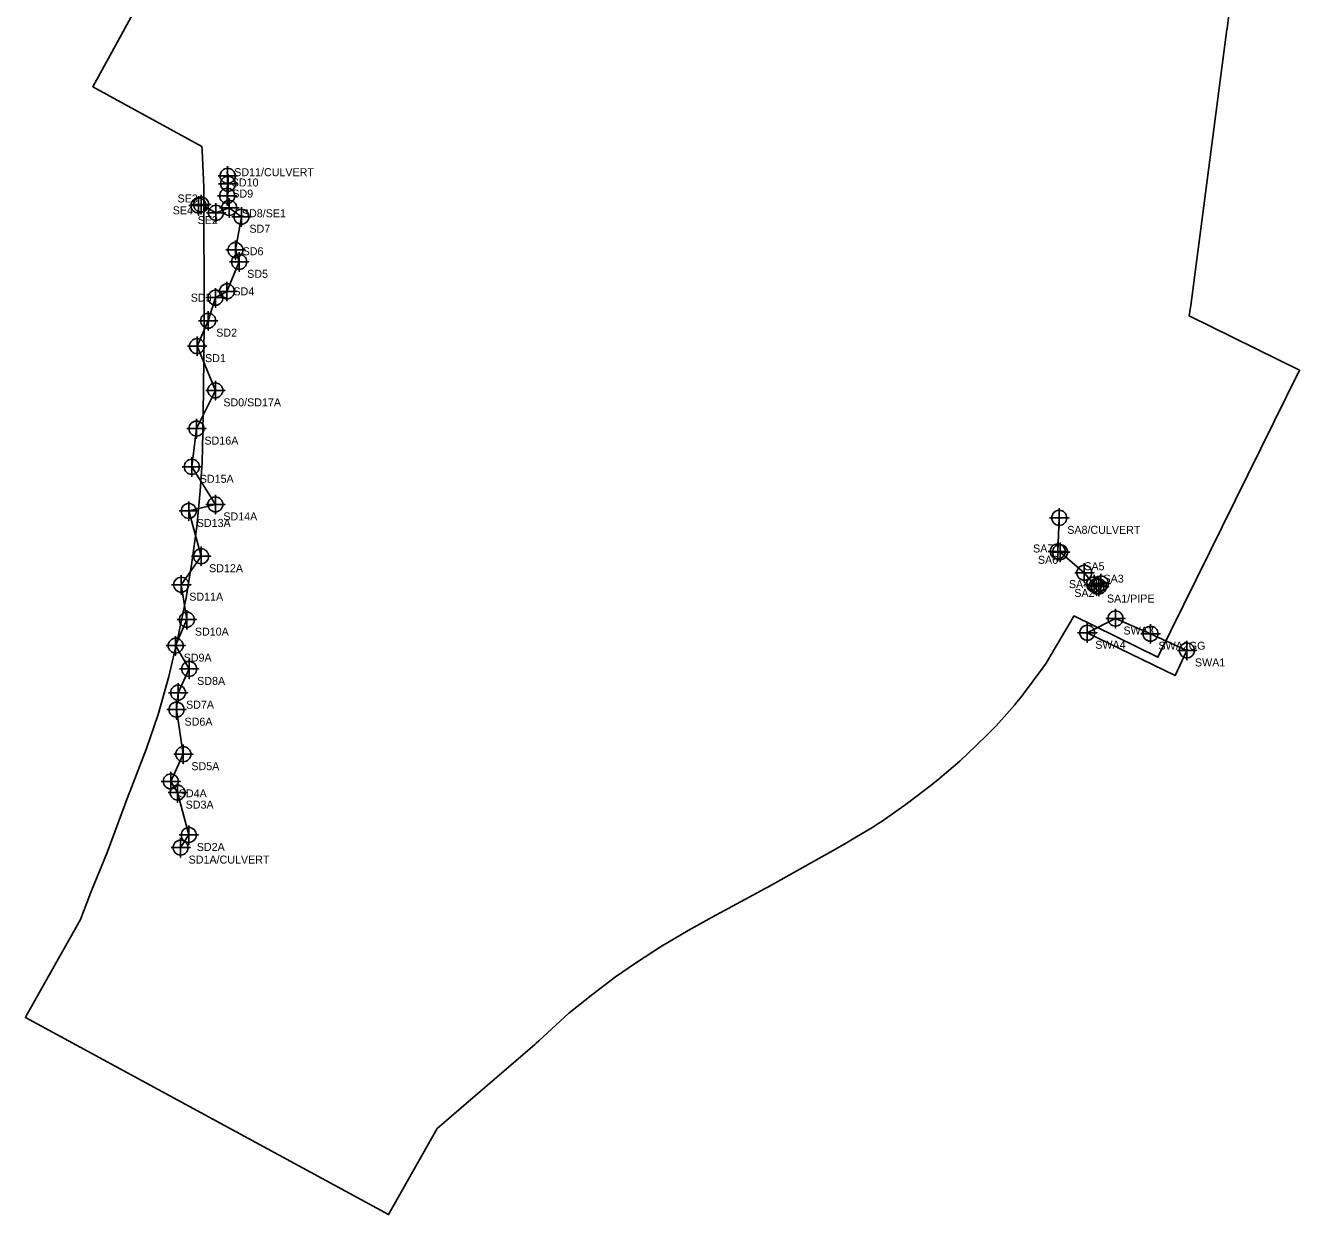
# Model space of a CAD drawing. Extents: x 2074690 to 2076562, y 742141 to 745115.
# Drawn here: x 2074690 to 2076283, y 742141 to 743628 of the extents above; entities that cross this region are included whole.
import ezdxf

# ---------------------------------------------------------------- set-up
doc = ezdxf.new("R2010")
doc.units = 0
for name, color, linetype in [('Default', 7, 'Continuous'), ('Exist Hydro Jurisdictional Stream or Body of Water Mitigable', 7, 'Continuous'), ('Exist Hydro Jurisdictional Stream or Body of Water Mitigable Cogo Comment', 7, 'Continuous'), ('Exist Hydro Jurisdictional Stream or Body of Water Mitigable Cogo Point CELL', 7, 'Continuous'), ('Exist Hydro Jurisdictional Stream or Body of Water NonMitigable', 7, 'Continuous'), ('Exist Hydro Jurisdictional Stream or Body of Water NonMitigable Cogo Comment', 7, 'Continuous'), ('Exist Hydro Jurisdictional Stream or Body of Water NonMitigable Cogo Point CELL', 7, 'Continuous')]:
    doc.layers.add(name, color=color, linetype=linetype)

msp = doc.modelspace()

# ---------------------------------------------------------------- linework, layer by layer
at = {"layer": 'Default'}
msp.add_lwpolyline([(2076207.6, 743748.1), (2076192, 743623.9), (2076191.8, 743622.9), (2076146.7, 743278), (2076146.6, 743277.9), (2076146, 743273.2), (2076144.7, 743264.8), (2076282.6, 743196.9), (2076105.7, 742838.1), (2076000.7, 742889.8), (2076000.1, 742888.7), (2075998, 742885.1), (2075997.2, 742883.7), (2075971.9, 742840.6), (2075965.8, 742830.9), (2075960.5, 742823.3), (2075937.7, 742792.4), (2075935.4, 742789.4), (2075927.1, 742779.3), (2075926.6, 742778.7), (2075903.3, 742752.3), (2075894.9, 742743.4), (2075892, 742740.6), (2075866.7, 742716.3), (2075860, 742710.2), (2075857.9, 742708.3), (2075830.5, 742685), (2075822.6, 742678.6), (2075822.2, 742678.3), (2075794.4, 742657.1), (2075788.1, 742652.4), (2075760.8, 742633.2), (2075756.8, 742630.5), (2075748.1, 742625), (2075721.8, 742609.3), (2075719.3, 742607.9), (2075719.2, 742607.8), (2075691.1, 742591.6), (2075688.7, 742590.3), (2075617.1, 742550.3), (2075615, 742549.1), (2075548.4, 742513), (2075518.7, 742496.6), (2075484.1, 742476.1), (2075454.2, 742456.6), (2075427.6, 742438.6), (2075399.3, 742416.9), (2075369.6, 742393), (2075331.8, 742358.3), (2075328.6, 742355.4), (2075327.1, 742354.1), (2075235, 742274.8), (2075204.8, 742248.9), (2075144.1, 742141.3), (2074690.4, 742387.6), (2074692.7, 742391.9), (2074720.6, 742441.5), (2074759.2, 742510.4), (2074771.8, 742543.3), (2074773.4, 742547.2), (2074792.4, 742594), (2074820.2, 742668.1), (2074820.8, 742669.7), (2074841.8, 742724.2), (2074856.1, 742766.6), (2074869.7, 742814.1), (2074881, 742862.3), (2074891.4, 742912.3), (2074898.4, 742956.5), (2074904.6, 743001.7), (2074908.8, 743045.7), (2074911.2, 743081.8), (2074912.2, 743118.8), (2074912.9, 743172.5), (2074913.6, 743257.2), (2074913.3, 743426.4), (2074911.1, 743471.5), (2074910.7, 743476.9), (2074774.6, 743551.4), (2074966.7, 743902.2)], dxfattribs=at)
at = {"layer": 'Exist Hydro Jurisdictional Stream or Body of Water Mitigable'}
for points in [[(2074884.3, 742600.1), (2074894.5, 742615.9), (2074880.6, 742668.8), (2074872, 742682.9), (2074887.7, 742716.9), (2074879.2, 742772.6), (2074881.1, 742793.8), (2074895, 742823.5), (2074878.1, 742852.6), (2074892.1, 742885.1), (2074885.1, 742928.8), (2074909.9, 742964.4), (2074894.5, 743021), (2074927.7, 743029.2), (2074898.3, 743076.2), (2074904.1, 743124), (2074927.7, 743171.8), (2074904.8, 743227.1), (2074918.8, 743258.9), (2074928, 743287.7), (2074942.2, 743295.6), (2074957.5, 743332.5), (2074952.8, 743347.3), (2074960.3, 743388.9), (2074945.1, 743400), (2074942.5, 743421.3), (2074943.6, 743430.1), (2074942.5, 743444.9)], [(2074945.1, 743400), (2074928.5, 743393.8), (2074909.9, 743404.2), (2074906.7, 743402.8)], [(2075982.3, 743012.4), (2075980.4, 742970.4), (2075983.3, 742969.5), (2076013.6, 742943.8), (2076025.9, 742929.2), (2076034.2, 742930.4), (2076029, 742927.1), (2076031.9, 742926.5)]]:
    msp.add_lwpolyline(points, dxfattribs=at)
at = {"layer": 'Exist Hydro Jurisdictional Stream or Body of Water Mitigable Cogo Point CELL'}
for points in [[(2074943.1, 743452), (2074943.1, 743428), (2074943.1, 743440), (2074955.1, 743440), (2074931.1, 743440)], [(2074943.6, 743442.1), (2074943.6, 743418.1), (2074943.6, 743430.1), (2074955.6, 743430.1), (2074931.6, 743430.1)], [(2074942.5, 743427), (2074942.5, 743403), (2074942.5, 743415), (2074954.5, 743415), (2074930.5, 743415)], [(2074906.7, 743414.8), (2074906.7, 743390.8), (2074906.7, 743402.8), (2074918.7, 743402.8), (2074894.7, 743402.8)], [(2074909.9, 743416.2), (2074909.9, 743392.2), (2074909.9, 743404.2), (2074921.9, 743404.2), (2074897.9, 743404.2)], [(2074928.5, 743405.8), (2074928.5, 743381.8), (2074928.5, 743393.8), (2074940.5, 743393.8), (2074916.5, 743393.8)], [(2074945.1, 743412), (2074945.1, 743388), (2074945.1, 743400), (2074957.1, 743400), (2074933.1, 743400)], [(2074960.3, 743400.9), (2074960.3, 743376.9), (2074960.3, 743388.9), (2074972.3, 743388.9), (2074948.3, 743388.9)], [(2074952.8, 743359.3), (2074952.8, 743335.3), (2074952.8, 743347.3), (2074964.8, 743347.3), (2074940.8, 743347.3)], [(2074957.5, 743344.5), (2074957.5, 743320.5), (2074957.5, 743332.5), (2074969.5, 743332.5), (2074945.5, 743332.5)], [(2074928, 743299.7), (2074928, 743275.7), (2074928, 743287.7), (2074940, 743287.7), (2074916, 743287.7)], [(2074942.2, 743307.6), (2074942.2, 743283.6), (2074942.2, 743295.6), (2074954.2, 743295.6), (2074930.2, 743295.6)], [(2074918.8, 743270.9), (2074918.8, 743246.9), (2074918.8, 743258.9), (2074930.8, 743258.9), (2074906.8, 743258.9)], [(2074904.8, 743239.1), (2074904.8, 743215.1), (2074904.8, 743227.1), (2074916.8, 743227.1), (2074892.8, 743227.1)], [(2074927.7, 743183.8), (2074927.7, 743159.8), (2074927.7, 743171.8), (2074939.7, 743171.8), (2074915.7, 743171.8)], [(2074904.1, 743136), (2074904.1, 743112), (2074904.1, 743124), (2074916.1, 743124), (2074892.1, 743124)], [(2074898.3, 743088.2), (2074898.3, 743064.2), (2074898.3, 743076.2), (2074910.3, 743076.2), (2074886.3, 743076.2)], [(2074927.7, 743041.2), (2074927.7, 743017.2), (2074927.7, 743029.2), (2074939.7, 743029.2), (2074915.7, 743029.2)], [(2074894.5, 743033), (2074894.5, 743009), (2074894.5, 743021), (2074906.5, 743021), (2074882.5, 743021)], [(2075982.3, 743024.4), (2075982.3, 743000.4), (2075982.3, 743012.4), (2075994.3, 743012.4), (2075970.3, 743012.4)], [(2074909.9, 742976.4), (2074909.9, 742952.4), (2074909.9, 742964.4), (2074921.9, 742964.4), (2074897.9, 742964.4)], [(2075980.4, 742982.4), (2075980.4, 742958.4), (2075980.4, 742970.4), (2075992.4, 742970.4), (2075968.4, 742970.4)], [(2075983.3, 742981.5), (2075983.3, 742957.5), (2075983.3, 742969.5), (2075995.3, 742969.5), (2075971.3, 742969.5)], [(2076013.6, 742955.8), (2076013.6, 742931.8), (2076013.6, 742943.8), (2076025.6, 742943.8), (2076001.6, 742943.8)], [(2074885.1, 742940.8), (2074885.1, 742916.8), (2074885.1, 742928.8), (2074897.1, 742928.8), (2074873.1, 742928.8)], [(2076025.9, 742941.2), (2076025.9, 742917.2), (2076025.9, 742929.2), (2076037.9, 742929.2), (2076013.9, 742929.2)], [(2076029, 742939.1), (2076029, 742915.1), (2076029, 742927.1), (2076041, 742927.1), (2076017, 742927.1)], [(2076031.9, 742938.5), (2076031.9, 742914.5), (2076031.9, 742926.5), (2076043.9, 742926.5), (2076019.9, 742926.5)], [(2076034.2, 742942.4), (2076034.2, 742918.4), (2076034.2, 742930.4), (2076046.2, 742930.4), (2076022.2, 742930.4)], [(2074892.1, 742897.1), (2074892.1, 742873.1), (2074892.1, 742885.1), (2074904.1, 742885.1), (2074880.1, 742885.1)], [(2074878.1, 742864.6), (2074878.1, 742840.6), (2074878.1, 742852.6), (2074890.1, 742852.6), (2074866.1, 742852.6)], [(2074895, 742835.5), (2074895, 742811.5), (2074895, 742823.5), (2074907, 742823.5), (2074883, 742823.5)], [(2074881.1, 742805.8), (2074881.1, 742781.8), (2074881.1, 742793.8), (2074893.1, 742793.8), (2074869.1, 742793.8)], [(2074879.2, 742784.6), (2074879.2, 742760.6), (2074879.2, 742772.6), (2074891.2, 742772.6), (2074867.2, 742772.6)], [(2074887.7, 742728.9), (2074887.7, 742704.9), (2074887.7, 742716.9), (2074899.7, 742716.9), (2074875.7, 742716.9)], [(2074872, 742694.9), (2074872, 742670.9), (2074872, 742682.9), (2074884, 742682.9), (2074860, 742682.9)], [(2074880.6, 742680.8), (2074880.6, 742656.8), (2074880.6, 742668.8), (2074892.6, 742668.8), (2074868.6, 742668.8)], [(2074894.5, 742627.9), (2074894.5, 742603.9), (2074894.5, 742615.9), (2074906.5, 742615.9), (2074882.5, 742615.9)], [(2074884.3, 742612.1), (2074884.3, 742588.1), (2074884.3, 742600.1), (2074896.3, 742600.1), (2074872.3, 742600.1)]]:
    msp.add_lwpolyline(points, dxfattribs=at)
for centre in [(2074943.1, 743440), (2074943.6, 743430.1), (2074942.5, 743415), (2074906.7, 743402.8), (2074909.9, 743404.2), (2074945.1, 743400), (2074928.5, 743393.8), (2074960.3, 743388.9), (2074952.8, 743347.3), (2074957.5, 743332.5), (2074928, 743287.7), (2074942.2, 743295.6), (2074918.8, 743258.9), (2074904.8, 743227.1), (2074927.7, 743171.8), (2074904.1, 743124), (2074898.3, 743076.2), (2074894.5, 743021), (2074927.7, 743029.2), (2075982.3, 743012.4), (2075980.4, 742970.4), (2075983.3, 742969.5), (2074909.9, 742964.4), (2076013.6, 742943.8), (2074885.1, 742928.8), (2076025.9, 742929.2), (2076029, 742927.1), (2076031.9, 742926.5), (2076034.2, 742930.4), (2074892.1, 742885.1), (2074878.1, 742852.6), (2074895, 742823.5), (2074881.1, 742793.8), (2074879.2, 742772.6), (2074887.7, 742716.9), (2074872, 742682.9), (2074880.6, 742668.8), (2074894.5, 742615.9), (2074884.3, 742600.1)]:
    msp.add_circle(centre, 9.38, dxfattribs=at)
at = {"layer": 'Exist Hydro Jurisdictional Stream or Body of Water NonMitigable'}
msp.add_lwpolyline([(2076141.9, 742846.6), (2076096.3, 742867.5), (2076052.6, 742886.5), (2076017.3, 742868.7)], dxfattribs=at)
msp.add_lwpolyline([(2076017.3, 742868.7), (2076052.6, 742886.5), (2076096.3, 742867.5), (2076141.9, 742846.6), (2076127.1, 742815.1)], close=True, dxfattribs=at)
at = {"layer": 'Exist Hydro Jurisdictional Stream or Body of Water NonMitigable Cogo Point CELL'}
for points in [[(2076052.6, 742898.5), (2076052.6, 742874.5), (2076052.6, 742886.5), (2076064.6, 742886.5), (2076040.6, 742886.5)], [(2076017.3, 742880.7), (2076017.3, 742856.7), (2076017.3, 742868.7), (2076029.3, 742868.7), (2076005.3, 742868.7)], [(2076096.3, 742879.5), (2076096.3, 742855.5), (2076096.3, 742867.5), (2076108.3, 742867.5), (2076084.3, 742867.5)], [(2076141.9, 742858.6), (2076141.9, 742834.6), (2076141.9, 742846.6), (2076153.9, 742846.6), (2076129.9, 742846.6)]]:
    msp.add_lwpolyline(points, dxfattribs=at)
for centre in [(2076052.6, 742886.5), (2076017.3, 742868.7), (2076096.3, 742867.5), (2076141.9, 742846.6)]:
    msp.add_circle(centre, 9.38, dxfattribs=at)

# ---------------------------------------------------------------- texts
at = {"layer": 'Exist Hydro Jurisdictional Stream or Body of Water Mitigable Cogo Comment'}
for s, p in [('SD10', (2074948.2, 743426.7)), ('SD11/CULVERT', (2074951.3, 743439.6)), ('SD9', (2074948.9, 743412.8)), ('SE3', (2074880.5, 743406.7)), ('SE4', (2074874.4, 743391.9)), ('SE2', (2074905.6, 743379.7)), ('SD8/SE1', (2074960.9, 743388.2)), ('SD7', (2074970.3, 743368.9)), ('SD6', (2074961.8, 743340.7)), ('SD5', (2074967.5, 743312.5)), ('SD4', (2074950.3, 743290.6)), ('SD3', (2074897, 743282.7)), ('SD2', (2074928.8, 743238.9)), ('SD1', (2074914.8, 743207.1)), ('SD0/SD17A', (2074937.7, 743151.8)), ('SD16A', (2074914.1, 743104)), ('SD15A', (2074908.3, 743056.2)), ('SD13A', (2074904.5, 743001)), ('SD14A', (2074937.7, 743009.2)), ('SA8/CULVERT', (2075992.3, 742992.4)), ('SA7', (2075949.6, 742969.1)), ('SA6', (2075955.6, 742954.9)), ('SD12A', (2074919.9, 742944.4)), ('SA5', (2076013.6, 742946.9)), ('SA4', (2075994.4, 742924.5)), ('SA3', (2076037.6, 742931.4)), ('SD11A', (2074895.1, 742908.8)), ('SA2', (2076001.1, 742913.5)), ('SA1/PIPE', (2076041.9, 742906.5)), ('SD10A', (2074902.1, 742865.1)), ('SD9A', (2074888.1, 742832.6)), ('SD8A', (2074905, 742803.5)), ('SD7A', (2074891.1, 742773.8)), ('SD6A', (2074889.2, 742752.6)), ('SD5A', (2074897.7, 742696.9)), ('SD4A', (2074882, 742662.9)), ('SD3A', (2074890.6, 742648.8)), ('SD2A', (2074904.5, 742595.9)), ('SD1A/CULVERT', (2074894.3, 742580.1))]:
    msp.add_text(s, height=10, dxfattribs=at).set_placement(p)
at = {"layer": 'Exist Hydro Jurisdictional Stream or Body of Water NonMitigable Cogo Comment'}
for s, p in [('SWA3', (2076062.6, 742866.5)), ('SWA4', (2076027.3, 742848.7)), ('SWA2GG', (2076106.3, 742847.5)), ('SWA1', (2076151.9, 742826.6))]:
    msp.add_text(s, height=10, dxfattribs=at).set_placement(p)

doc.saveas('drawing.dxf')
